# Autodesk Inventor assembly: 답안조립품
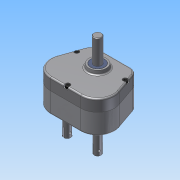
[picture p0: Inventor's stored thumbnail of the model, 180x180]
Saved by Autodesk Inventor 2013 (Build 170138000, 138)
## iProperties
Created: 2014-12
Part Number: 답안조립품
Document SubType Name: Assembly
Designer: Administrator
Author: Administrator
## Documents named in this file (14)
- C:\Users\Administrator\Desktop\441209V1039\답안조립품.iam
- C:\Users\Administrator\Desktop\441209V1039\M 5 x 35.ipt
- C:\Users\Administrator\Desktop\441209V1039\멈춤링.ipt
- C:\Users\Administrator\Desktop\441209V1039\메인기어.ipt
- C:\Users\Administrator\Desktop\441209V1039\메인축.ipt
- C:\Users\Administrator\Desktop\441209V1039\베어링- 6202.ipt
- C:\Users\Administrator\Desktop\441209V1039\베어링- 6203.ipt
- C:\Users\Administrator\Desktop\441209V1039\본체.ipt
- C:\Users\Administrator\Desktop\441209V1039\서브기어.ipt
- C:\Users\Administrator\Desktop\441209V1039\서브축.ipt
- C:\Users\Administrator\Desktop\441209V1039\오일시일-D-15.ipt
- C:\Users\Administrator\Desktop\441209V1039\오일시일-D-17.ipt
- C:\Users\Administrator\Desktop\441209V1039\커버.ipt
- C:\Users\Administrator\Desktop\441209V1039\키5x5.ipt
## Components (15 placed, 6 different names)
1. KS B 1003 - 미터 M 5 x 35:1
2. KS B 2023 6202 - 15 x 35 x 11:1
3. KS B 2023 6202 - 15 x 35 x 11:2
4. KS B 2804 D D - 15 30 7:1
5. KS B 2804 D D - 15 30 7:2
6. KS B 2804 D D - 17 30 8:1
7. KS B 2023 6203 - 17 x 40 x 12:1
8. KS B 2023 6203 - 17 x 40 x 12:2
9. KS B 2023 6203 - 17 x 40 x 12:3
10. KS B 2023 6203 - 17 x 40 x 12:4
11. KS B 1336 17 x 1:1
12. KS B 1336 17 x 1:2
13. KS B 1336 17 x 1:3
14. KS B 1003 - 미터 M 5 x 35:2
15. KS B 1003 - 미터 M 5 x 35:3
